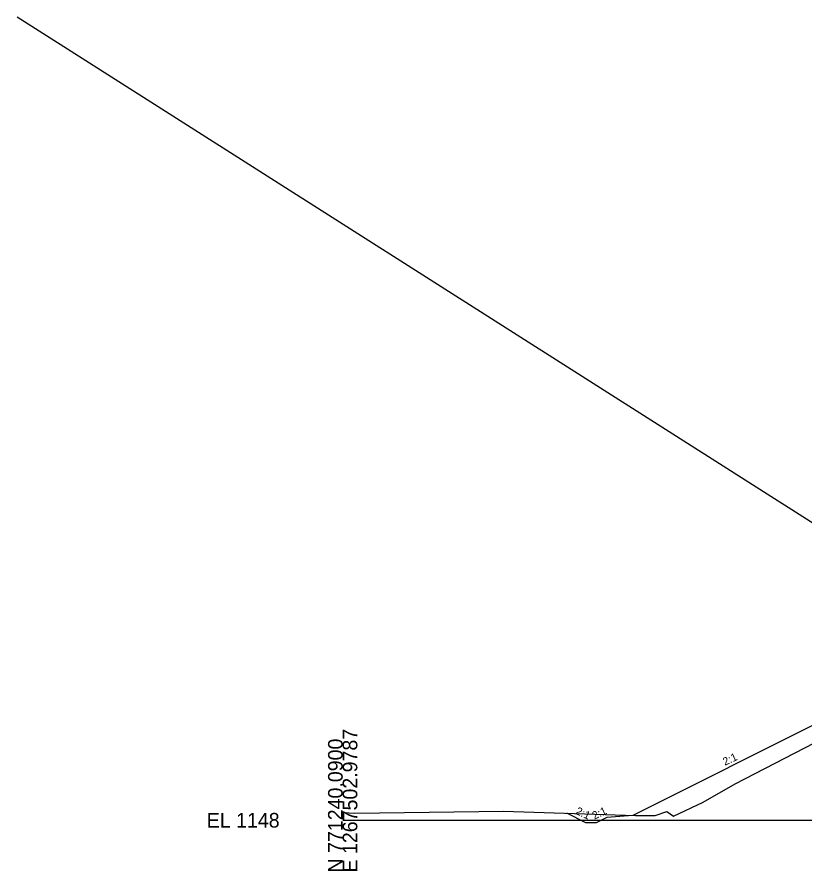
# Model space of a CAD drawing. Extents: x -3833 to 1267678, y -522 to 773248.
# Drawn here: x -62.2 to 88.4, y 6490.3 to 6653.6 of the extents above; entities that cross this region are included whole.
import ezdxf

# ---------------------------------------------------------------- set-up
doc = ezdxf.new("R2010")
doc.units = 0
for name, color, linetype in [('Exist Cross Section Cell', 7, 'Continuous'), ('Exist XS Ground Line', 7, 'Continuous'), ('Prop XS Finish Grade', 7, 'Continuous'), ('Prop XS Label Text', 7, 'Continuous'), ('Scratch_Level_1', 7, 'Continuous')]:
    doc.layers.add(name, color=color, linetype=linetype)

msp = doc.modelspace()

# ---------------------------------------------------------------- linework, layer by layer
at = {"layer": 'Exist Cross Section Cell'}
msp.add_line((0, 6500), (150, 6500), dxfattribs=at)
at = {"layer": 'Exist XS Ground Line'}
for p, q in [((75.03, 6506.99), (97.91, 6518.83)), ((75.03, 6506.99), (97.91, 6518.83)), ((68.93, 6503.43), (75.03, 6506.99)), ((68.93, 6503.43), (75.03, 6506.99)), ((63.27, 6500.79), (68.93, 6503.43)), ((63.27, 6500.79), (68.93, 6503.43)), ((0, 6501.47), (2.34, 6501.38)), ((2.34, 6501.38), (30.72, 6501.71)), ((30.72, 6501.71), (56.01, 6500.92)), ((30.72, 6501.71), (56.01, 6500.92)), ((56.01, 6500.92), (59.74, 6500.91)), ((56.01, 6500.92), (59.74, 6500.91)), ((59.74, 6500.91), (62, 6501.7)), ((59.74, 6500.91), (62, 6501.7)), ((62, 6501.7), (63.27, 6500.79)), ((62, 6501.7), (63.27, 6500.79))]:
    msp.add_line(p, q, dxfattribs=at)
at = {"layer": 'Prop XS Finish Grade'}
msp.add_line((92.02, 6519.2), (55.48, 6500.93), dxfattribs=at)
msp.add_lwpolyline([(55.48, 6500.93), (50.48, 6500.52), (48.48, 6499.52), (46.48, 6499.52), (42.86, 6501.33)], dxfattribs=at)
at = {"layer": 'Scratch_Level_1'}
msp.add_line((150, 6518.54), (-62.25, 6653.6), dxfattribs=at)

# ---------------------------------------------------------------- texts
at = {"layer": 'Exist Cross Section Cell'}
for s, p in [('E 1267502.9787', (2.8, 6490)), ('N 771240.0900', (0, 6490))]:
    msp.add_text(s, height=2.8, rotation=90, dxfattribs=at).set_placement(p)
msp.add_text('EL 1148', height=2.8, dxfattribs=at).set_placement((-26, 6498.6))
at = {"layer": 'Prop XS Label Text'}
for rotation, p in [(24.9367, (73.08, 6510.41)), (335.0633, (44.39, 6501.26)), (24.9367, (48.12, 6500.11))]:
    msp.add_text('2:1', height=1.5, rotation=rotation, dxfattribs=at).set_placement(p)

doc.saveas('drawing.dxf')
